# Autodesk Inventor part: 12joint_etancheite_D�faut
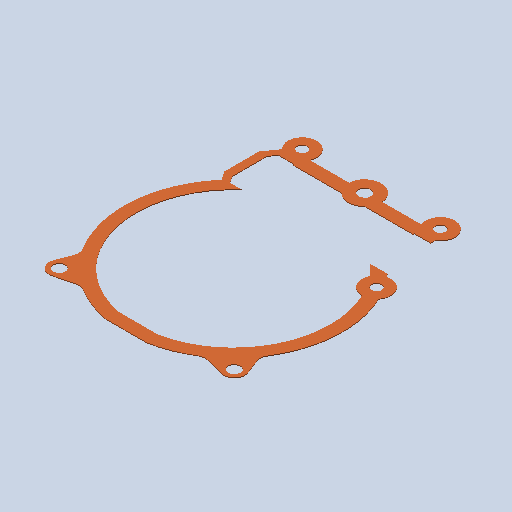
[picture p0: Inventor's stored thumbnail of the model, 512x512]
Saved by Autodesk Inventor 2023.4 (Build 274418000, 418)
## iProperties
Created: 2011-01
Part Number: 12joint_etancheite_D�faut
Document SubType Name: Modeling
Designer: eric
Density: 1 g/cm^3
Mass: 1.00407 g
Surface Area: 53.7215 cm^2
Volume: 1.00407 cm^3
Material: Générique
Appearance: 255,128,64_1
Author: eric
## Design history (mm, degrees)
feature "Base1"
node "Corps solides"
node "Corps surfaciques"
node "Solide1"
